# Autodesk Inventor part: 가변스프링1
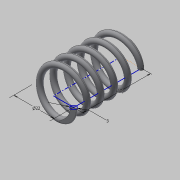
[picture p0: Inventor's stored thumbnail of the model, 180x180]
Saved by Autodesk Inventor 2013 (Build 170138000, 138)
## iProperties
Created: 2015-02
Part Number: 가변스프링1
Material: 강철, 탄소
Document SubType Name: Modeling
Designer: Administrator
Density: 7.87 g/cm^3
Mass: 18.7444 g
Surface Area: 32.4012 cm^2
Volume: 2.38175 cm^3
Author: Administrator
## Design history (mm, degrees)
sketch "스케치1"
  geometry: L1 (0, 0)-(11, 0); L2 (11, 0)-(11, 25.508); L3 (11, 25.508)-(0, 25.508); L4 (0, 25.508)-(0, 0); C1 r 1.5 at (11, 0)
  constraints: 8 end point, 2 parallel, 1 centre point, 1 coincident, 1 horizontal, 1 perpendicular
  dimensions: "d0" = 25.50829 distance of L1.end L2.end (derived); "d2" = 22 diameter of L2 L4; "d3" = 3 diameter of C1
feature "코일1" sketch "스케치1" pitch "d4" = 10; turns "d6" = 5; dims "d5" = 25.50829 (= d0), "d7" = 0, angle "d8" = 90 deg, angle "d9" = 90 deg, "d10" = 0, "d11" = 0
node "작업 평면1"
sketch "스케치2"
  geometry: L1 (-12.5, 0)-(-9.5, 0) reference; L2 (-12.5, 0)-(-9.5, 0) reference; 1 further point
  constraints: 2 horizontal alignment
extrude "돌출1" cut sketch "스케치2" distance "d13" = 10; taper "d14" = 0 deg
node "작업 평면2"
sketch "스케치3"
  geometry: L1 (-9.5, 0)-(-12.5, 0) reference; 1 further point
  constraints: 1 horizontal alignment
extrude "돌출2" cut sketch "스케치3" distance "d16" = 10; taper "d17" = 0 deg
node "솔리드1"
node "절단 모서리 투영1"
node "절단 모서리 투영2"
node "절단 모서리 투영3"
other parameters: "d12" = 0, "d15" = 25.50829 (= d0)
